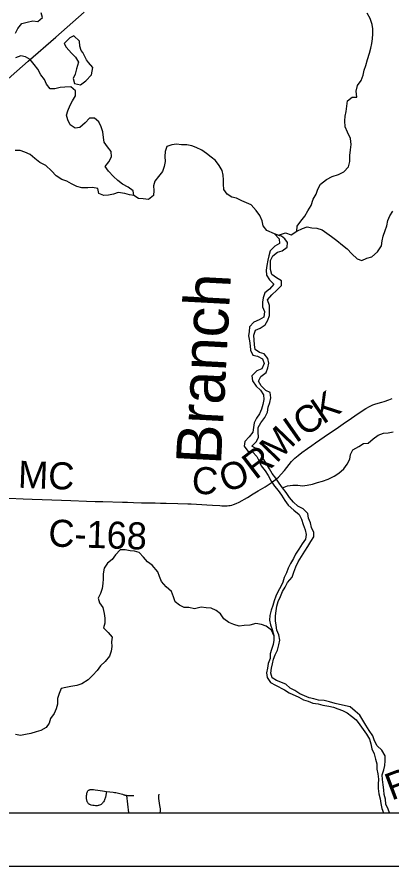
# Model space of a CAD drawing. Extents: x 0 to 34, y 0 to 22.
# Drawn here: x 17.698 to 18.485, y 9.81 to 11.594 of the extents above; entities that cross this region are included whole.
import ezdxf

# ---------------------------------------------------------------- set-up
doc = ezdxf.new("R2010")
doc.units = 0
for name, color, linetype in [('GM_X_Corporation', 7, 'Continuous'), ('GM_X_County_Road', 7, 'Continuous'), ('GM_X_County_Road_Text', 7, 'Continuous'), ('GM_X_Minor_Lake', 7, 'Continuous'), ('GM_X_Minor_River', 7, 'Continuous'), ('GM_X_Minor_River_Text', 7, 'Continuous'), ('GM_X_Rail_Line', 7, 'Continuous'), ('GM_X_Township_Road', 7, 'Continuous'), ('SH_Data', 7, 'Continuous')]:
    doc.layers.add(name, color=color, linetype=linetype)

msp = doc.modelspace()

# ---------------------------------------------------------------- linework, layer by layer
at = {"layer": 'GM_X_Corporation'}
msp.add_lwpolyline([(13.1219, 9.9214), (18.7033, 9.9214), (18.7026, 10.0146), (18.6993, 10.4973), (18.6948, 10.9413), (18.6983, 11.0124), (18.6977, 11.0152), (18.6975, 11.0178), (18.6974, 11.0209), (18.6969, 11.1033), (18.6969, 11.1473), (18.6964, 11.248), (18.6957, 11.2928), (18.6956, 11.3092), (18.6959, 11.3398), (18.696, 11.356), (18.6958, 11.3799), (18.6956, 11.3921), (18.695, 11.4676), (18.6946, 11.511), (18.6946, 11.5569), (18.6947, 11.64)], dxfattribs=at)
at = {"layer": 'GM_X_County_Road'}
msp.add_lwpolyline([(17.6811, 10.5829), (17.7116, 10.5817), (17.7302, 10.5808), (17.7509, 10.5799), (17.7922, 10.5784), (17.8115, 10.5778), (17.8444, 10.5768), (17.8624, 10.5762), (17.8673, 10.576), (17.8704, 10.576), (17.879, 10.5756), (17.9199, 10.5747), (17.9309, 10.5746), (17.9432, 10.5741), (17.96, 10.5734), (17.9749, 10.5731), (17.9842, 10.5729), (17.9885, 10.5728), (18.0003, 10.5726), (18.012, 10.5723), (18.0363, 10.5719), (18.0574, 10.5711), (18.0642, 10.5707), (18.0871, 10.5694), (18.0977, 10.5687), (18.1095, 10.568), (18.1249, 10.5672), (18.1293, 10.567), (18.1329, 10.5669), (18.1363, 10.5669), (18.1403, 10.5671), (18.1435, 10.5672), (18.1468, 10.5677), (18.1503, 10.5683), (18.1534, 10.5694), (18.1591, 10.5714), (18.1657, 10.5747), (18.1829, 10.5843), (18.1951, 10.5918), (18.2056, 10.5983), (18.22, 10.6071), (18.2324, 10.6152), (18.2414, 10.6218), (18.2479, 10.6274), (18.254, 10.6335), (18.2605, 10.641), (18.2655, 10.6473), (18.2705, 10.6536), (18.2758, 10.6598), (18.2827, 10.667), (18.2892, 10.6728), (18.2971, 10.6789), (18.3088, 10.6872), (18.3179, 10.6936), (18.326, 10.6994), (18.344, 10.7116), (18.3743, 10.7323), (18.3839, 10.7391), (18.4019, 10.7514), (18.4159, 10.7606), (18.432, 10.7711), (18.4396, 10.7755), (18.4464, 10.7788), (18.4529, 10.7812), (18.4654, 10.785), (18.4701, 10.7864), (18.4801, 10.7897), (18.4834, 10.791), (18.487, 10.7927)], dxfattribs=at)
at = {"layer": 'GM_X_Minor_Lake'}
msp.add_line((17.8443, 11.5041), (17.837, 11.5196), dxfattribs=at)
msp.add_lwpolyline([(17.837, 11.5196), (17.8335, 11.5237), (17.8307, 11.5332), (17.8299, 11.5438), (17.818, 11.555), (17.8093, 11.5504), (17.7973, 11.5388), (17.8016, 11.5309), (17.8127, 11.5185), (17.8215, 11.5099), (17.8273, 11.4993), (17.8237, 11.4856), (17.8208, 11.4738), (17.8167, 11.4647), (17.8191, 11.4544), (17.832, 11.4516), (17.8433, 11.46), (17.8549, 11.4727), (17.8574, 11.4883), (17.8489, 11.4984), (17.8443, 11.5041)], dxfattribs=at)
at = {"layer": 'GM_X_Minor_River'}
for points in [[(17.6952, 11.5604), (17.6997, 11.5703), (17.7083, 11.5803), (17.72, 11.5835), (17.7313, 11.5859), (17.7419, 11.5849), (17.7517, 11.593), (17.7493, 11.6028)], [(18.287, 11.1444), (18.2872, 11.1547), (18.2951, 11.165), (18.3037, 11.1754), (18.31, 11.1872), (18.317, 11.1979), (18.321, 11.2113), (18.3274, 11.222), (18.3307, 11.2326), (18.3366, 11.2426), (18.3494, 11.253), (18.361, 11.2588), (18.3742, 11.2631), (18.3855, 11.269), (18.3953, 11.2793), (18.3982, 11.2908), (18.3984, 11.3029), (18.3998, 11.3154), (18.4012, 11.3261), (18.3995, 11.3386), (18.3929, 11.3522), (18.3883, 11.3635), (18.3877, 11.3757), (18.3884, 11.3856), (18.3905, 11.3954), (18.3919, 11.4069), (18.3929, 11.4183), (18.4027, 11.426), (18.4125, 11.4261), (18.4113, 11.4386), (18.4145, 11.45), (18.4216, 11.4611), (18.426, 11.4718), (18.4282, 11.4824), (18.4315, 11.492), (18.4355, 11.5049), (18.4395, 11.5186), (18.4421, 11.5289), (18.4446, 11.5388), (18.4456, 11.5487), (18.4466, 11.559), (18.4462, 11.5692), (18.4449, 11.5787), (18.4406, 11.5912), (18.4348, 11.6025)], [(17.9441, 11.2194), (17.9425, 11.2292), (17.9318, 11.2363), (17.92, 11.243), (17.9104, 11.2505), (17.9009, 11.2591), (17.8909, 11.27), (17.8836, 11.2802), (17.8911, 11.2901), (17.897, 11.3005), (17.8961, 11.3115), (17.8884, 11.3216), (17.8815, 11.3314), (17.8799, 11.3413), (17.879, 11.3526), (17.8751, 11.3636), (17.8704, 11.3742), (17.8609, 11.3813), (17.851, 11.3819), (17.8413, 11.3719), (17.8304, 11.3619), (17.8206, 11.3607), (17.8099, 11.3674), (17.8052, 11.378), (17.8021, 11.3878), (17.805, 11.3973), (17.8098, 11.4088), (17.815, 11.4183), (17.8213, 11.4283), (17.8216, 11.4393), (17.8116, 11.4475), (17.7992, 11.4466), (17.7889, 11.4461), (17.778, 11.4433), (17.7678, 11.4432), (17.7601, 11.4534), (17.7562, 11.4632), (17.7485, 11.473), (17.7419, 11.4843), (17.7342, 11.4941), (17.7262, 11.5046), (17.7159, 11.5106), (17.706, 11.5123), (17.6954, 11.5084)], [(18.2397, 11.1382), (18.2233, 11.1452), (18.2156, 11.155), (18.2136, 11.1656), (18.2086, 11.1769), (18.2013, 11.1875), (18.1905, 11.1995), (18.1806, 11.2035), (18.1707, 11.208), (18.1601, 11.2132), (18.1502, 11.2157), (18.1403, 11.2217), (18.1333, 11.2318), (18.1325, 11.2428), (18.1327, 11.2523), (18.1319, 11.2618), (18.1299, 11.2717), (18.1237, 11.2822), (18.116, 11.2924), (18.1064, 11.2995), (18.0969, 11.3077), (18.0866, 11.3141), (18.0752, 11.32), (18.0657, 11.3237), (18.0554, 11.3258), (18.0444, 11.3257), (18.0338, 11.3267), (18.0236, 11.3259), (18.013, 11.3219), (18.0097, 11.3116), (18.0091, 11.301), (18.0096, 11.2904), (18.0078, 11.2797), (18.0045, 11.2694), (17.9956, 11.2591), (17.9881, 11.2495), (17.9856, 11.2396), (17.986, 11.2297), (17.9854, 11.2191), (17.9745, 11.211), (17.9639, 11.212), (17.954, 11.213), (17.9441, 11.2194), (17.9346, 11.2208), (17.9251, 11.2233), (17.9111, 11.2251), (17.9013, 11.2219), (17.8907, 11.2199), (17.8809, 11.2194), (17.8702, 11.2231), (17.8682, 11.2337), (17.8568, 11.2358), (17.847, 11.2353), (17.8345, 11.2352), (17.8242, 11.2377), (17.8128, 11.2437), (17.8033, 11.2489), (17.7923, 11.2529), (17.7808, 11.2604), (17.7705, 11.2709), (17.7586, 11.2818), (17.746, 11.2884), (17.7361, 11.2971), (17.7258, 11.3053), (17.7147, 11.3101), (17.7052, 11.3138), (17.6942, 11.314)], [(18.2479, 11.1354), (18.2628, 11.1407), (18.2745, 11.1367), (18.287, 11.1444), (18.2983, 11.1495), (18.3081, 11.1534), (18.3179, 11.1512), (18.3289, 11.1502), (18.3396, 11.1466), (18.3495, 11.1398), (18.3598, 11.1327), (18.3709, 11.1245), (18.3824, 11.1148), (18.3923, 11.1073), (18.4023, 11.0964), (18.4134, 11.0863), (18.4236, 11.0822), (18.4338, 11.0873), (18.4447, 11.0901), (18.4564, 11.1005), (18.4646, 11.1131), (18.4663, 11.1237), (18.4685, 11.1333), (18.4725, 11.1455), (18.4762, 11.1554), (18.4783, 11.1664), (18.4824, 11.1767), (18.4883, 11.1863)], [(18.3112, 10.5406), (18.3099, 10.5509), (18.3, 10.5606), (18.2889, 10.5658), (18.2794, 10.5748), (18.2713, 10.5846), (18.2644, 10.5948), (18.2563, 10.6045), (18.2497, 10.6147), (18.2428, 10.6249), (18.2351, 10.6347), (18.229, 10.6448), (18.222, 10.6565), (18.2158, 10.6663), (18.2119, 10.6762), (18.2035, 10.6859), (18.1924, 10.6923), (18.2018, 10.7019), (18.2059, 10.7114), (18.2054, 10.7217), (18.2053, 10.7315), (18.2112, 10.7415), (18.2194, 10.7526), (18.225, 10.7636), (18.2267, 10.7743), (18.23, 10.7842), (18.2318, 10.7941), (18.2309, 10.8047), (18.2214, 10.8092), (18.2118, 10.8189), (18.2064, 10.8287), (18.2112, 10.8387), (18.2221, 10.8468), (18.2258, 10.8571), (18.228, 10.8666), (18.226, 10.8768), (18.2179, 10.8866), (18.2084, 10.8891), (18.1989, 10.8955), (18.1976, 10.9049), (18.1966, 10.9254), (18.1995, 10.9361), (18.2097, 10.9404), (18.2203, 10.947), (18.2258, 10.9569), (18.2291, 10.9672), (18.2294, 10.9775), (18.2289, 10.9881), (18.2253, 10.9998), (18.2339, 11.0102), (18.2448, 11.0198), (18.2545, 11.0301), (18.2541, 11.0396), (18.2438, 11.0463), (18.2342, 11.0531), (18.2314, 11.0633), (18.231, 11.0731), (18.2316, 11.0826), (18.236, 11.0926), (18.2458, 11.1003), (18.2556, 11.1031), (18.2661, 11.1108), (18.2668, 11.1206), (18.2612, 11.128), (18.2547, 11.1337), (18.2512, 11.1343), (18.2397, 11.1382), (18.2497, 11.1277), (18.2505, 11.1182), (18.2407, 11.1124), (18.2306, 11.1028), (18.2277, 11.0925), (18.2259, 11.083), (18.2238, 11.0723), (18.2224, 11.062), (18.2232, 11.0518), (18.229, 11.042), (18.2386, 11.0326), (18.2289, 11.0222), (18.2191, 11.0145), (18.2162, 11.0043), (18.2144, 10.9947), (18.2145, 10.9849), (18.2188, 10.9751), (18.2174, 10.9636), (18.2073, 10.9578), (18.1963, 10.9528), (18.187, 10.9432), (18.1867, 10.9333), (18.1853, 10.9238), (18.1873, 10.9136), (18.1886, 10.9033), (18.1894, 10.8938), (18.1945, 10.8833), (18.204, 10.8811), (18.2142, 10.8755), (18.2181, 10.8657), (18.2133, 10.855), (18.2024, 10.8507), (18.1923, 10.8403), (18.1932, 10.8297)], [(18.1932, 10.8297), (18.2009, 10.8184), (18.2104, 10.8098), (18.2166, 10.8), (18.2171, 10.7905), (18.2149, 10.7795), (18.2124, 10.77), (18.2083, 10.7604), (18.2016, 10.7508), (18.1968, 10.7413), (18.1958, 10.7318), (18.1944, 10.7215), (18.1862, 10.7116), (18.1776, 10.702), (18.1762, 10.6921), (18.1838, 10.6819), (18.1933, 10.6801), (18.2025, 10.6704), (18.2072, 10.6605), (18.2118, 10.6507), (18.2199, 10.6402), (18.2261, 10.6304), (18.2327, 10.6187), (18.24, 10.6085), (18.2477, 10.5987), (18.2542, 10.5889), (18.2611, 10.578), (18.2684, 10.5679), (18.2803, 10.5577), (18.2918, 10.5488), (18.2968, 10.5386), (18.3, 10.5276), (18.3039, 10.5166), (18.3062, 10.5064), (18.3048, 10.4969), (18.2978, 10.4866), (18.2911, 10.4758), (18.284, 10.4655), (18.2795, 10.456), (18.2732, 10.4456), (18.2688, 10.4357), (18.2647, 10.4258), (18.2603, 10.4163), (18.2574, 10.4067), (18.2529, 10.3972), (18.2477, 10.3873), (18.2426, 10.3769), (18.2389, 10.367), (18.236, 10.3571), (18.233, 10.3472), (18.2298, 10.3365), (18.2295, 10.3267), (18.2311, 10.3168), (18.235, 10.3066), (18.2382, 10.2945), (18.2383, 10.2846), (18.2369, 10.2751), (18.2336, 10.2652), (18.2307, 10.2557), (18.2304, 10.2462), (18.2267, 10.2355), (18.2249, 10.2256), (18.2228, 10.2157), (18.224, 10.2059), (18.231, 10.1957), (18.2416, 10.1897), (18.2607, 10.1801), (18.2706, 10.1741), (18.2911, 10.1645), (18.3007, 10.1589), (18.3102, 10.156), (18.3201, 10.1519), (18.3318, 10.1505), (18.3413, 10.148), (18.3538, 10.1459), (18.3637, 10.1437), (18.3732, 10.14), (18.3827, 10.1363), (18.3922, 10.1315), (18.4018, 10.1248), (18.4113, 10.1173), (18.419, 10.1067), (18.426, 10.097), (18.4333, 10.0868), (18.4394, 10.0766), (18.4426, 10.0668), (18.4446, 10.0562), (18.4493, 10.0456), (18.4524, 10.0342), (18.4548, 10.0244), (18.4549, 10.0134), (18.4573, 10.0032), (18.4586, 9.9922), (18.4579, 9.9819), (18.458, 9.9724), (18.4593, 9.9614), (18.4617, 9.9512), (18.4633, 9.9409), (18.4657, 9.9307), (18.4692, 9.9214)], [(18.2563, 10.6045), (18.2669, 10.6088), (18.2786, 10.6101), (18.2888, 10.6102), (18.2987, 10.6092), (18.3085, 10.6101), (18.3195, 10.6121), (18.3304, 10.6157), (18.3406, 10.6184), (18.3523, 10.6231), (18.3651, 10.6294), (18.3752, 10.6352), (18.3854, 10.6444), (18.3925, 10.6547), (18.3984, 10.6651), (18.3994, 10.6749), (18.4042, 10.6845), (18.4167, 10.6918), (18.4272, 10.698), (18.437, 10.6985), (18.4475, 10.7078), (18.4577, 10.7151), (18.4686, 10.7198), (18.4788, 10.7203), (18.4894, 10.7227)], [(18.4816, 9.9214), (18.4786, 9.929), (18.4739, 9.9396), (18.473, 9.9506), (18.4703, 9.9604), (18.4698, 9.9699), (18.4685, 9.9801), (18.4665, 9.9919), (18.466, 10.0014), (18.4693, 10.0116), (18.4715, 10.0212), (18.4725, 10.0307), (18.4724, 10.0413), (18.4651, 10.0534), (18.4555, 10.0624), (18.4501, 10.0729), (18.4466, 10.0831), (18.4385, 10.0948), (18.4319, 10.1058), (18.4254, 10.1163), (18.4192, 10.1265), (18.4096, 10.1351), (18.3985, 10.1441), (18.3891, 10.1463), (18.367, 10.1513), (18.3552, 10.155), (18.3442, 10.1579), (18.3325, 10.1585), (18.3226, 10.1614), (18.3127, 10.1636), (18.293, 10.1717), (18.2826, 10.1788), (18.2728, 10.1833), (18.2632, 10.1923), (18.2442, 10.1996), (18.2346, 10.2052), (18.2319, 10.2154), (18.2337, 10.2253), (18.2358, 10.2348), (18.2376, 10.2444), (18.2409, 10.2539), (18.2457, 10.2634), (18.2486, 10.2745), (18.2508, 10.2848), (18.2491, 10.2958), (18.2449, 10.3056), (18.2429, 10.3158), (18.242, 10.3253), (18.2415, 10.3359), (18.2433, 10.3458), (18.2447, 10.3561), (18.2476, 10.3656), (18.2524, 10.3763), (18.2568, 10.3866), (18.2624, 10.3962), (18.2672, 10.4057), (18.277, 10.4168), (18.2806, 10.4275), (18.2847, 10.4389), (18.2895, 10.4493), (18.2965, 10.4603), (18.3032, 10.4714), (18.3096, 10.481), (18.3163, 10.4917), (18.3222, 10.5017), (18.3225, 10.5111), (18.3178, 10.521), (18.3154, 10.5308), (18.3112, 10.5406)], [(18.2382, 10.2945), (18.2331, 10.3054), (18.2224, 10.3141), (18.2125, 10.3177), (18.2004, 10.3195), (18.1876, 10.3163), (18.1758, 10.315), (18.1653, 10.3138), (18.1542, 10.3174), (18.1436, 10.3219), (18.1333, 10.3293), (18.1263, 10.3395), (18.1168, 10.3466), (18.1065, 10.3514), (18.0959, 10.3524), (18.0857, 10.3535), (18.0717, 10.3506), (18.0599, 10.3532), (18.0501, 10.3534), (18.0402, 10.3582), (18.0306, 10.365), (18.0275, 10.3756), (18.0228, 10.3869), (18.0117, 10.3963), (18.0021, 10.4079), (17.9978, 10.4185), (17.9943, 10.4283), (17.9824, 10.4419), (17.9725, 10.4493), (17.964, 10.4591), (17.9552, 10.4689), (17.9453, 10.4714), (17.9359, 10.4721), (17.9256, 10.4746), (17.9154, 10.4741), (17.9053, 10.4641), (17.8986, 10.4542), (17.8884, 10.4465), (17.8814, 10.4358), (17.8792, 10.4236), (17.8797, 10.4133), (17.8791, 10.4035), (17.8773, 10.3928), (17.8736, 10.3829), (17.8692, 10.373), (17.8719, 10.3631), (17.8789, 10.3529), (17.8813, 10.3408), (17.8833, 10.331), (17.8827, 10.32), (17.8801, 10.3101), (17.8897, 10.3007), (17.8985, 10.2909), (17.8971, 10.281), (17.8976, 10.2712), (17.8966, 10.2616), (17.8925, 10.251), (17.8839, 10.2399), (17.8742, 10.2306), (17.8667, 10.221), (17.8574, 10.2111), (17.8476, 10.2011), (17.8348, 10.193), (17.8243, 10.1894), (17.8118, 10.187), (17.8008, 10.1853), (17.791, 10.183), (17.787, 10.1723), (17.7837, 10.162), (17.7831, 10.1498), (17.7809, 10.1403), (17.7761, 10.13), (17.769, 10.1197), (17.7657, 10.1101), (17.7598, 10.1006), (17.7485, 10.0944), (17.7386, 10.092), (17.7273, 10.0884), (17.716, 10.086), (17.7054, 10.0844), (17.6948, 10.0861)]]:
    msp.add_lwpolyline(points, dxfattribs=at)
at = {"layer": 'GM_X_Rail_Line'}
msp.add_lwpolyline([(17.6553, 11.4431), (17.7218, 11.5012), (17.7796, 11.5518), (17.8396, 11.6046)], dxfattribs=at)
at = {"layer": 'GM_X_Township_Road'}
msp.add_line((17.9337, 9.9214), (17.9295, 9.9581), dxfattribs=at)
for points in [[(17.8865, 9.9667), (17.8842, 9.9548), (17.8836, 9.9524), (17.8831, 9.9508), (17.8825, 9.9492), (17.882, 9.948), (17.8813, 9.9465), (17.8801, 9.9445), (17.8791, 9.9432), (17.8781, 9.9418), (17.8767, 9.9404), (17.875, 9.9391), (17.8736, 9.9383), (17.8721, 9.9377), (17.87, 9.9371), (17.8688, 9.9369), (17.8668, 9.9366), (17.8659, 9.9365), (17.8641, 9.9365), (17.8631, 9.9365), (17.8604, 9.9367), (17.8575, 9.9371), (17.8541, 9.9378), (17.8529, 9.9382), (17.8514, 9.9388), (17.8505, 9.9392), (17.8497, 9.9398), (17.8489, 9.9404), (17.8484, 9.9408), (17.8478, 9.9416), (17.847, 9.9427), (17.8464, 9.9438), (17.846, 9.9447), (17.8455, 9.9462), (17.8451, 9.9478), (17.8448, 9.9492), (17.8447, 9.95), (17.8445, 9.9512), (17.8445, 9.9522), (17.8444, 9.9547), (17.8446, 9.958), (17.8449, 9.9604), (17.8452, 9.9619), (17.8454, 9.9631), (17.8457, 9.9641), (17.8459, 9.9647), (17.8462, 9.9655), (17.8468, 9.9666), (17.8474, 9.9675), (17.8481, 9.9683), (17.8488, 9.9689), (17.8495, 9.9694), (17.8505, 9.9698), (17.8511, 9.9701), (17.8522, 9.9703), (17.8537, 9.9706), (17.8544, 9.9706), (17.8556, 9.9706), (17.8572, 9.9706), (17.8588, 9.9705), (17.8626, 9.9701), (17.8684, 9.9694), (17.8782, 9.9679), (17.8865, 9.9667), (17.8938, 9.9657), (17.9005, 9.9649), (17.9031, 9.9645), (17.906, 9.9641), (17.9091, 9.9634), (17.9117, 9.9629), (17.9147, 9.9621), (17.9198, 9.9606), (17.9227, 9.9597), (17.9241, 9.9594), (17.9252, 9.959), (17.9263, 9.9588), (17.928, 9.9584), (17.9295, 9.9581)], [(17.9295, 9.9581), (17.9305, 9.958), (17.9316, 9.9579), (17.9338, 9.9578), (17.9349, 9.9577), (17.9367, 9.9577), (17.9373, 9.9577), (17.9391, 9.9577), (17.94, 9.9578), (17.9419, 9.958), (17.9442, 9.9582)], [(17.9988, 9.9214), (17.9991, 9.9222), (17.9994, 9.9231), (17.9997, 9.9244), (17.9999, 9.9259), (17.9999, 9.9272), (17.9999, 9.9285), (17.9998, 9.9297), (17.9997, 9.9305), (17.9995, 9.932), (17.9994, 9.9333), (17.9988, 9.9372), (17.9966, 9.9519), (17.9965, 9.9531), (17.9964, 9.9546), (17.9964, 9.9554), (17.9964, 9.9564), (17.9965, 9.9574), (17.9972, 9.9609)]]:
    msp.add_lwpolyline(points, dxfattribs=at)
at = {"layer": 'SH_Data'}
msp.add_line((12.556, 9.8098), (19.556, 9.8098), dxfattribs=at)

# ---------------------------------------------------------------- texts
at = {"layer": 'GM_X_County_Road_Text'}
for s, height, rotation, p in [('K', 0.0568, 34.1689, (18.3418, 10.7369)), ('C', 0.0568, 34.2508, (18.3033, 10.7106)), ('I', 0.0568, 35.0086, (18.2843, 10.6973)), ('M', 0.0568, 46.1898, (18.2439, 10.6548)), ('R', 0.0568, 37.3717, (18.1997, 10.6201)), ('MC', 0.05682, 357.8134, (17.6998, 10.605)), ('O', 0.0568, 20.1469, (18.1364, 10.5939)), ('C', 0.0568, 356.2231, (18.0644, 10.5933)), ('C-168', 0.05682, 358.0735, (17.7636, 10.4816)), ('RD', 0.05682, 20.6136, (18.4857, 9.9469))]:
    msp.add_text(s, height=height, rotation=rotation, dxfattribs=at).set_placement(p)
at = {"layer": 'GM_X_Minor_River_Text'}
msp.add_text('Branch', height=0.09473, rotation=86.9762, dxfattribs=at).set_placement((18.127, 10.6518))

doc.saveas('drawing.dxf')
